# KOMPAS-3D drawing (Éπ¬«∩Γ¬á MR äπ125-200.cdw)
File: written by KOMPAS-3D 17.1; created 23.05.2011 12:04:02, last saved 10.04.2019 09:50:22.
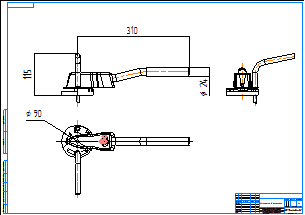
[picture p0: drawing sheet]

Sheet 1: A1, landscape

Title block, sheet 1: name: Рукоятка MR Ду125-200; material: Внимание! Данный продукт является объектом авторского права ООО «Торговый Дом АДЛ». / Запрещается изменение, копирование, распространение / (в том числе путем копирования на другие сайты и ресурсы в Интернете) / или любое иное использование информации и объектов без предварительного / согласия правообладателя (ООО «Торговый Дом АДЛ»).; scale: 1:1; sheets: 1; organisation: ООО "Торговый дом АДЛ"; sheet format: A1; stored path: \\adlc.lan\data\АДЛ_ПКД\3D-модели\ADL production\Дисковые поворотные затворы ГРАНВЭЛ\Рукоятки ГРАНВЭЛ\тип MR\KOMPAS 2D\Рукоятка MR Ду125-200.cdw

Views: Спереди 1, Проекционный вид 2, Проекционный вид 3
Dimensions and other numbers on the sheet: 115; 90; 310; 24; 1:1; 1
